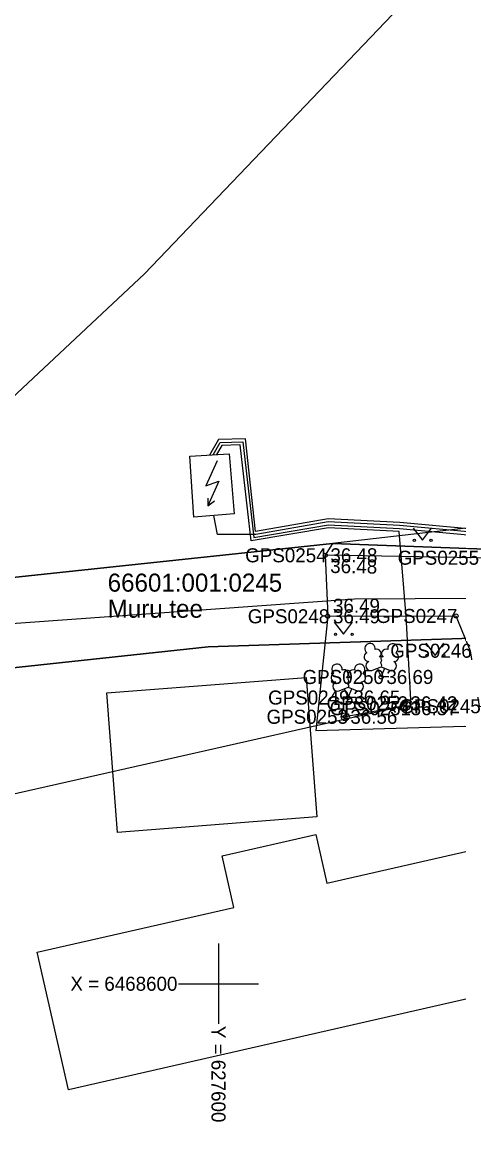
# Model space of a CAD drawing. Extents: x 626224 to 628280, y 6467750 to 6471135.
# Drawn here: x 627590.2 to 627612, y 6468592.2 to 6468647.9 of the extents above; entities that cross this region are included whole.
import ezdxf

# ---------------------------------------------------------------- set-up
doc = ezdxf.new("R2010")
doc.units = 0
for name, color, linetype in [('HALJASTUS', 7, 'Continuous'), ('Hoone Kõrval- või tootmishoone', 7, 'Continuous'), ('KORGUS-EH2000', 7, 'Continuous'), ('KPKAABEL', 7, 'Continuous'), ('MOOTKORG-EH2000', 7, 'Continuous'), ('MOOTMPUNKT', 7, 'Continuous'), ('MOOTNR', 7, 'Continuous'), ('MOOTPIIR', 7, 'Continuous'), ('MPKAABEL', 7, 'Continuous'), ('MPOHULIIN', 7, 'Continuous'), ('PIIR', 7, 'Continuous'), ('POST', 7, 'Continuous'), ('PUU', 7, 'Continuous'), ('RAJATIS', 7, 'Continuous'), ('TEE', 7, 'Continuous'), ('Tee Muu tee Kruuskate', 7, 'Continuous'), ('VORK', 7, 'Continuous')]:
    doc.layers.add(name, color=color, linetype=linetype)

msp = doc.modelspace()

# ---------------------------------------------------------------- linework, layer by layer
at = {"layer": 'HALJASTUS'}
for p, q in [((627609.706, 6468622.722), (627610.17, 6468622.115)), ((627610.17, 6468622.115), (627610.615, 6468622.722)), ((627605.774, 6468618.031), (627606.238, 6468617.424)), ((627606.238, 6468617.424), (627606.683, 6468618.031)), ((627610.334, 6468616.978), (627610.798, 6468616.371)), ((627610.798, 6468616.371), (627611.243, 6468616.978))]:
    msp.add_line(p, q, dxfattribs=at)
for centre in [(627609.769, 6468622.115), (627610.598, 6468622.115), (627605.837, 6468617.424), (627606.665, 6468617.424), (627610.397, 6468616.371), (627611.225, 6468616.371)]:
    msp.add_circle(centre, 0.055, dxfattribs=at)
at = {"layer": 'Hoone Kõrval- või tootmishoone'}
for points in [[(627604.902, 6468608.315), (627594.965, 6468607.55), (627594.43, 6468614.499), (627604.366, 6468615.264)], [(627620.142, 6468608.374), (627621.737, 6468601.37), (627592.514, 6468594.714), (627590.952, 6468601.57), (627600.763, 6468603.805), (627600.176, 6468606.382), (627604.856, 6468607.448), (627605.41, 6468605.018)]]:
    msp.add_lwpolyline(points, close=True, dxfattribs=at)
at = {"layer": 'KORGUS-EH2000'}
for centre in [(627605.321, 6468621.364), (627605.451, 6468618.323), (627611.844, 6468618.339), (627609.324, 6468613.741)]:
    msp.add_circle(centre, 0.1, dxfattribs=at)
at = {"layer": 'KPKAABEL'}
msp.add_lwpolyline([(627685.782, 6468640.643), (627682.599, 6468638.441), (627678.043, 6468635.809), (627672.046, 6468634.344), (627660.214, 6468631.662), (627657.997, 6468630.954), (627658.117, 6468626.708), (627657.689, 6468626.13), (627652.495, 6468625.008), (627640.455, 6468623.259), (627628.481, 6468622.246), (627623.048, 6468622.007), (627612.632, 6468622.516), (627609.034, 6468622.858), (627605.474, 6468623.034), (627601.854, 6468622.409), (627599.956, 6468622.4), (627599.775, 6468623.347)], dxfattribs=at)
at = {"layer": 'MOOTMPUNKT'}
for centre in [(627605.321, 6468621.364), (627605.451, 6468618.323), (627611.844, 6468618.339), (627608.112, 6468615.297), (627606.465, 6468614.271), (627609.308, 6468613.983), (627609.324, 6468613.741), (627606.316, 6468613.313)]:
    msp.add_circle(centre, 0.1, dxfattribs=at)
at = {"layer": 'MOOTPIIR'}
msp.add_lwpolyline([(627656.533, 6468628.521), (627633.238, 6468625.152), (627620.768, 6468623.676), (627605.69, 6468621.95), (627605.321, 6468621.364), (627605.451, 6468618.323), (627604.849, 6468612.629), (627612.287, 6468612.849), (627619.934, 6468611.546), (627644.92, 6468614.927), (627687.389, 6468622.904)], dxfattribs=at)
at = {"layer": 'MPKAABEL'}
for points in [[(627685.699, 6468640.768), (627682.519, 6468638.568), (627677.987, 6468635.95), (627672.012, 6468634.49), (627660.175, 6468631.807), (627657.844, 6468631.063), (627657.966, 6468626.756), (627657.602, 6468626.265), (627652.468, 6468625.156), (627640.438, 6468623.408), (627628.471, 6468622.396), (627623.048, 6468622.157), (627612.643, 6468622.666), (627609.045, 6468623.008), (627605.465, 6468623.185), (627601.841, 6468622.559), (627601.344, 6468627.176), (627599.992, 6468627.142), (627599.551, 6468626.364)], [(627599.73, 6468626.375), (627600.081, 6468626.994), (627601.209, 6468627.023), (627601.759, 6468622.259), (627605.483, 6468622.883), (627609.023, 6468622.708), (627612.621, 6468622.366), (627623.048, 6468621.857), (627628.491, 6468622.096), (627640.472, 6468623.11), (627652.522, 6468624.86), (627657.776, 6468625.995), (627658.268, 6468626.66), (627658.15, 6468630.845), (627660.253, 6468631.517), (627672.08, 6468634.198), (627673.058, 6468632.736)], [(627609.316, 6468613.862), (627609.613, 6468613.883), (627609.363, 6468618.32), (627609.012, 6468622.559), (627605.492, 6468622.733), (627601.628, 6468622.084), (627601.075, 6468626.869), (627600.169, 6468626.846), (627599.908, 6468626.386)]]:
    msp.add_lwpolyline(points, dxfattribs=at)
at = {"layer": 'MPOHULIIN'}
for p, q in [((627609.316, 6468613.862), (627604.874, 6468612.859)), ((627604.874, 6468612.859), (627562.342, 6468603.253))]:
    msp.add_line(p, q, dxfattribs=at)
at = {"layer": 'PIIR'}
for points in [[(627615.39, 6468662.67), (627619.6, 6468659.76), (627596.31, 6468635.4), (627586.23, 6468625.97), (627582.22, 6468631.69), (627537.09, 6468671.63), (627549.96, 6468707.41), (627579.16, 6468687.58)], [(627654.85, 6468663.52), (627663.66, 6468662.2), (627686.69, 6468632.75), (627684.35, 6468632.16), (627652.69, 6468624.22), (627623.24, 6468621.3), (627605.69, 6468621.95), (627588.94, 6468620.18), (627586.23, 6468625.97), (627596.31, 6468635.4), (627619.6, 6468659.76), (627624.98, 6468665.39), (627633.24, 6468674.95), (627637.73, 6468680.5), (627640.48, 6468683.65), (627644.86, 6468680.34)], [(627599.49, 6468616.8), (627643.52, 6468618.24), (627653, 6468577.43), (627666.94, 6468517.08), (627608.44, 6468499.25), (627602.15, 6468514.88), (627588.44, 6468509.87), (627563.73, 6468583.75), (627555.29, 6468612.05)]]:
    msp.add_lwpolyline(points, close=True, dxfattribs=at)
msp.add_lwpolyline([(627401.5, 6468603.97), (627489.68, 6468613.41), (627577.55, 6468622.81), (627581.38, 6468622.85), (627583, 6468623.57), (627584.27, 6468624.13), (627586.23, 6468625.97), (627588.94, 6468620.18), (627605.69, 6468621.95), (627623.24, 6468621.3), (627652.69, 6468624.22), (627684.35, 6468632.16), (627688.18, 6468626.77), (627643.52, 6468618.24), (627599.49, 6468616.8), (627555.29, 6468612.05), (627411.34, 6468595.13)], dxfattribs=at)
at = {"layer": 'POST'}
msp.add_lwpolyline([(627609.316, 6468613.862), (627606.316, 6468613.313)], dxfattribs=at)
for centre, radius in [((627609.316, 6468613.862), 0.25), ((627606.316, 6468613.313), 0.2)]:
    msp.add_circle(centre, radius, dxfattribs=at)
at = {"layer": 'PUU'}
for p, q in [((627607.672, 6468615.632), (627608.117, 6468615.807)), ((627608.117, 6468615.807), (627608.557, 6468615.627)), ((627608.112, 6468615.297), (627607.937, 6468615.737)), ((627608.112, 6468615.297), (627608.292, 6468615.737)), ((627608.492, 6468615.297), (627608.112, 6468615.297)), ((627606.025, 6468614.606), (627606.47, 6468614.781)), ((627606.465, 6468614.271), (627606.29, 6468614.712)), ((627606.465, 6468614.271), (627606.645, 6468614.712)), ((627606.47, 6468614.781), (627606.91, 6468614.601)), ((627606.845, 6468614.271), (627606.465, 6468614.271))]:
    msp.add_line(p, q, dxfattribs=at)
for points in [[(627608.117, 6468616.302), (627608.097, 6468616.227), (627608.097, 6468616.207), (627608.107, 6468616.177), (627608.127, 6468616.142), (627608.132, 6468616.122), (627608.117, 6468616.087), (627608.092, 6468616.037), (627608.087, 6468616.012), (627608.092, 6468615.997), (627608.102, 6468615.967), (627608.137, 6468615.907), (627608.142, 6468615.887), (627608.137, 6468615.867), (627608.122, 6468615.832), (627608.117, 6468615.807)], [(627606.47, 6468615.276), (627606.45, 6468615.201), (627606.45, 6468615.181), (627606.46, 6468615.151), (627606.48, 6468615.116), (627606.485, 6468615.096), (627606.47, 6468615.061), (627606.445, 6468615.012), (627606.44, 6468614.986), (627606.445, 6468614.971), (627606.455, 6468614.941), (627606.49, 6468614.882), (627606.495, 6468614.861), (627606.49, 6468614.842), (627606.475, 6468614.806), (627606.47, 6468614.781)]]:
    msp.add_lwpolyline(points, dxfattribs=at)
for centre, radius, start, end in [((627607.555, 6468616.711), 0.256, 111.5027, 232.5173), ((627607.555, 6468616.711), 0.256, 350.4856, 111.5002), ((627608.691, 6468616.702), 0.256, 67.6168, 188.6314), ((627608.691, 6468616.702), 0.256, 306.5997, 67.6143), ((627607.481, 6468616.299), 0.224, 111.4304, 274.4987), ((627607.889, 6468616.46), 0.224, 308.5041, 111.5725), ((627608.352, 6468616.456), 0.225, 67.7016, 230.5126), ((627608.758, 6468616.289), 0.224, 264.6183, 67.6866), ((627605.908, 6468615.686), 0.256, 111.5027, 232.5173), ((627605.908, 6468615.686), 0.256, 350.4856, 111.5002), ((627607.044, 6468615.677), 0.256, 67.6168, 188.6314), ((627607.044, 6468615.677), 0.256, 306.5997, 67.6143), ((627607.585, 6468615.855), 0.237, 111.5014, 291.5004), ((627608.116, 6468616.064), 0.237, 66.7655, 111.5015), ((627608.647, 6468615.847), 0.237, 247.6166, 67.6155), ((627605.834, 6468615.274), 0.224, 111.4304, 274.4987), ((627606.243, 6468615.435), 0.224, 308.5041, 111.5725), ((627606.469, 6468615.039), 0.237, 66.7655, 111.5015), ((627606.706, 6468615.431), 0.225, 67.7016, 230.5126), ((627607.111, 6468615.264), 0.224, 264.6183, 67.6866), ((627605.939, 6468614.83), 0.237, 111.5014, 291.5004), ((627607, 6468614.822), 0.237, 247.6166, 67.6155)]:
    msp.add_arc(centre, radius, start, end, dxfattribs=at)
at = {"layer": 'RAJATIS'}
for p, q in [((627599.938, 6468626.07), (627599.37, 6468624.828)), ((627599.37, 6468624.828), (627600.018, 6468625.053)), ((627600.018, 6468625.053), (627599.462, 6468623.824)), ((627599.462, 6468624.22), (627599.462, 6468623.824)), ((627599.462, 6468623.824), (627599.793, 6468624.088))]:
    msp.add_line(p, q, dxfattribs=at)
msp.add_lwpolyline([(627600.54, 6468626.425), (627600.777, 6468623.434), (627598.774, 6468623.261), (627598.569, 6468626.303)], close=True, dxfattribs=at)
at = {"layer": 'TEE'}
for points in [[(627655.323, 6468624.553), (627654.099, 6468624.153), (627644.239, 6468622.621), (627634.78, 6468621.504), (627626.983, 6468620.991), (627620.731, 6468620.942), (627612.855, 6468621.244), (627605.321, 6468621.364)], [(627605.451, 6468618.323), (627611.844, 6468618.339), (627612.555, 6468616.606), (627613.007, 6468613.838), (627616.056, 6468613.833), (627615.95, 6468616.377), (627616.311, 6468617.523), (627617.098, 6468617.911), (627625.292, 6468617.768), (627631.755, 6468618.128), (627635.301, 6468618.359), (627643.867, 6468619.473), (627648.701, 6468620.075), (627654.943, 6468621.043), (627656.855, 6468621.064)]]:
    msp.add_lwpolyline(points, dxfattribs=at)
at = {"layer": 'Tee Muu tee Kruuskate'}
msp.add_lwpolyline([(627655.281, 6468622.513), (627643.219, 6468620.707), (627634.046, 6468619.94), (627621.905, 6468619.252), (627606.783, 6468619.17), (627583.198, 6468617.485), (627569.985, 6468616.221), (627554.678, 6468614.391), (627502.881, 6468608.768), (627472.157, 6468604.735), (627458.252, 6468603.133), (627409.627, 6468597.894), (627406.06, 6468597.51)], dxfattribs=at)
at = {"layer": 'VORK'}
for p, q in [((627600, 6468602), (627600, 6468598)), ((627598, 6468600), (627602, 6468600))]:
    msp.add_line(p, q, dxfattribs=at)

# ---------------------------------------------------------------- texts
at = {"layer": 'KORGUS-EH2000'}
for s, rotation, p in [(' 36.48', 359.0898, (627605.307, 6468620.489)), (' 36.49', 0.1389, (627605.45, 6468618.498))]:
    msp.add_text(s, height=0.7, rotation=rotation, dxfattribs=at).set_placement(p)
msp.add_text(' 36.37', height=0.7, dxfattribs=at).set_placement((627609.324, 6468613.391))
at = {"layer": 'MOOTKORG-EH2000'}
for s, p in [(' 36.48', (627605.321, 6468621.014)), (' 36.49', (627605.451, 6468617.973)), (' 36.69', (627608.112, 6468614.947)), (' 36.65', (627606.465, 6468613.922)), (' 36.42', (627609.308, 6468613.633)), (' 36.37', (627609.324, 6468613.391)), (' 36.56', (627606.316, 6468612.963))]:
    msp.add_text(s, height=0.7, dxfattribs=at).set_placement(p)
at = {"layer": 'MOOTNR'}
for s, p in [('GPS0254 ', (627601.331, 6468621.014)), ('GPS0255 ', (627608.935, 6468620.894)), ('GPS0248 ', (627601.461, 6468617.973)), ('GPS0247 ', (627607.854, 6468617.989)), ('GPS0246 ', (627608.566, 6468616.256)), ('GPS0250 ', (627604.192, 6468614.947)), ('GPS0249 ', (627602.475, 6468613.922)), ('GPS0252 ', (627605.388, 6468613.633)), ('GPS0251 ', (627605.544, 6468613.391)), ('GPS0245 ', (627609.018, 6468613.488)), ('GPS0253 ', (627602.396, 6468612.963))]:
    msp.add_text(s, height=0.7, dxfattribs=at).set_placement(p)
at = {"layer": 'PIIR'}
for s, p in [('66601:001:0245', (627594.474, 6468619.552)), ('Muru tee', (627594.474, 6468618.252))]:
    msp.add_text(s, height=0.9, dxfattribs=at).set_placement(p)
at = {"layer": 'VORK'}
msp.add_text('X = 6468600', height=0.7, dxfattribs=at).set_placement((627592.615, 6468599.65))
msp.add_text('Y = 627600 ', height=0.7, rotation=270, dxfattribs=at).set_placement((627599.65, 6468597.9))

doc.saveas('drawing.dxf')
